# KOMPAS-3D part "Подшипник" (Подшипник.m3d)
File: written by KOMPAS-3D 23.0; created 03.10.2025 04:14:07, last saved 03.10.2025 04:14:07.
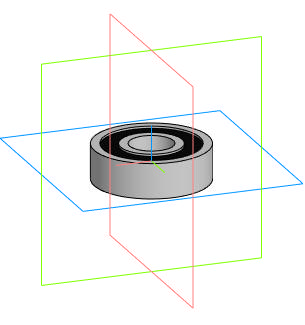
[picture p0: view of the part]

Document properties: Автор: Lost; Полное имя файла: C:\Users\Lost\Downloads\Telegram Desktop\ИМ-ИТ ЦД\ИМ-ИТ ЦД\Вариант 12\Подшипник.m3d

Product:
- Part/product: Подшипник

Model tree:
1. Операция без истории:1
